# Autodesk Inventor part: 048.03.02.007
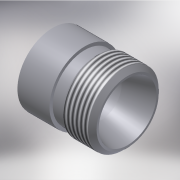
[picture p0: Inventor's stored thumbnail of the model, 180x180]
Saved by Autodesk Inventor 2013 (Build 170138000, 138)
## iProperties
Shininess: 25.0
Angle Display Precision: 2
Document Length Units: 11269
Document Angle Units: 11279
Document Time Units: 11290
Document Mass Units: 11283
Document Length Units Precision: 3
Document Angle Units Precision: 2
Created: 2002-04
Part Number: 048.03.02.007
Material: Steel, Mild
Description: Штуцер М33Х2 (Трd25)
Document SubType Name: Modeling
Designer: SaAlex
Density: 7.86 g/cm^3
Density: 0.0
Volumn: 0.0
Area: 0.0
PropertySet Name: Model Information
Control State: 0
Master: False
Checked Out: True
Checked Out Date: 2008-10-15
Last Check In Date: 2008-10-15
Title: Штуцер
Author: SaAlex
Comments: 048.03.02.007
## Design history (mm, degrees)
sketch "Sketch2"
  geometry: L1 (0, 0)-(35, 0) reference; L2 (35, 0)-(35, -9.5); L3 (35, -9.5)-(12.311, -9.5); L4 (12.311, -9.5)-(0, -13.5); L5 (0, -13.5)-(0, 0); L6 (35, 16.5)-(35, -16.5) reference; L7 (0, 14.5)-(0, -14.5) reference
  constraints: 10 end point, 2 horizontal, 2 parallel, 1 perpendicular
  dimensions: "d7" = 9.5 distance of L1.end L2.end; "d8" = 0 distance between parallel lines of L6 L2; "d9" = 0 distance between parallel lines of L7 L5; "d10" = 18 deg angle of L3 L4; "d13" = 13.5 distance from line of L4.end L1
sketch "Sketch3"
  geometry: C1 r 9.5 at (0, 0) reference; C2 r 16.5 at (0, 0) reference; C3 r 13 at (0, 0)
  constraints: 1 centre point, 1 coincident
  dimensions: "d14" = 26 diameter of C3
body "Solid1"
revolve "Revolution1" stored, may be unused: angle "d6" = 90 deg
revolve "Revolution2" stored, may be unused: angle "d12" = 90 deg
extrude "Extrusion1" cut sketch "Sketch3" distance "d15" = 5; taper "d16" = 0 deg
thread "Thread1" dims "d17" = 10, "d18" = 0
sketch "Sketch1"
  geometry: L1 (0, 0)-(-35, 0) reference; L2 (-35, 0)-(-35, 16.5); L3 (-35, 16.5)-(-20, 16.5); L4 (-20, 16.5)-(-20, 15); L5 (-20, 15)-(-15, 15); L6 (-15, 15)-(-13.5, 16.5); L7 (-13.5, 16.5)-(-2, 16.5); L8 (-2, 16.5)-(0, 14.5); L9 (0, 14.5)-(0, 0)
  constraints: 18 end point, 3 perpendicular, 2 horizontal, 2 parallel, 2 point on line
  dimensions: "d0" = 35 distance of L1.start L1.end; "d1" = 2 horizontal distance of L7.end L8.end; "d2" = 45 deg angle of L7 L8; "d3" = 45 deg angle of L5 L6; "d4" = 15 distance between parallel lines of L1 L5; "d5" = 16.5 distance of L1.end L2.end; "d19" = 20 distance from line of L3.end L9; "d20" = 5 distance of L4.end L5.end
